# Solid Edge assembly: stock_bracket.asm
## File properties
Author: Deepak Maini
Template: Normal.asm
Last saved by: MYPC
Revision: 30
Application: Solid Edge
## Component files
adjusting_screw_guide.par
adjusting_nut_handle.par
stock_support_roller.par
Stock_support_base.par
thrust_bearing.par
adjusting_screw_nut.par
support_adjusting_screw.par
support_roller_bracket.par
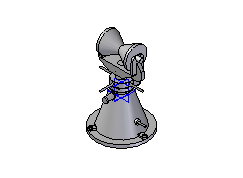
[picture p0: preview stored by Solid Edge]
